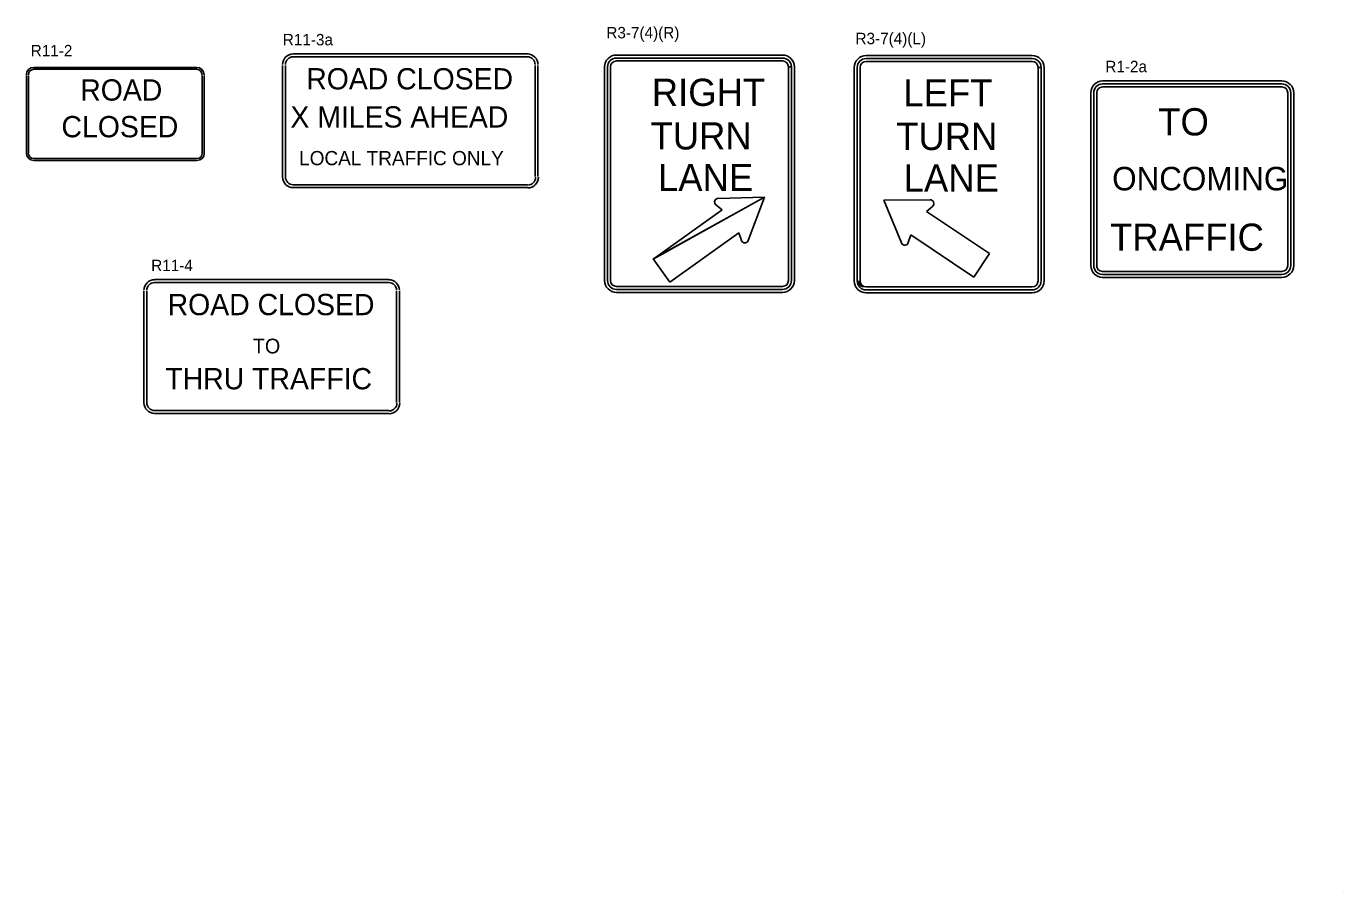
# Model space of a CAD drawing. Extents: x 1531.6 to 1538.58, y 1529.59 to 1539.33.
# Drawn here: x 1531.67 to 1538.58, y 1529.59 to 1534.14 of the extents above; entities that cross this region are included whole.
import ezdxf

# ---------------------------------------------------------------- set-up
doc = ezdxf.new("R2010")
doc.units = 0
for name, color, linetype in [('DETL-LINE', 7, 'Continuous'), ('DETL-NOTE', 7, 'Continuous'), ('TTLB-TEXT', 7, 'Continuous')]:
    doc.layers.add(name, color=color, linetype=linetype)

msp = doc.modelspace()

# ---------------------------------------------------------------- linework, layer by layer
at = {"layer": 'DETL-LINE'}
for p, q in [((1534.3016, 1533.9921), (1533.0731, 1533.9921)), ((1534.3016, 1533.9771), (1533.0731, 1533.9771)), ((1534.769, 1533.9859), (1535.6403, 1533.9859)), ((1534.769, 1533.9704), (1535.6403, 1533.9704)), ((1536.0788, 1533.9677), (1536.9501, 1533.9677)), ((1536.9502, 1533.9832), (1536.079, 1533.9832)), ((1536.9502, 1533.9676), (1536.079, 1533.9676)), ((1532.5663, 1533.9214), (1531.7123, 1533.9214)), ((1532.5663, 1533.9111), (1531.7123, 1533.9111)), ((1533.0173, 1533.9317), (1533.0173, 1533.3485)), ((1533.0322, 1533.9317), (1533.0322, 1533.3485)), ((1534.3425, 1533.3485), (1534.3425, 1533.9317)), ((1534.3574, 1533.3485), (1534.3574, 1533.9317)), ((1534.7068, 1532.8035), (1534.7068, 1533.9237)), ((1534.7224, 1532.8035), (1534.7224, 1533.9237)), ((1534.738, 1533.9237), (1534.738, 1532.8035)), ((1535.6403, 1533.9548), (1534.769, 1533.9548)), ((1535.687, 1533.9237), (1535.6714, 1533.9237)), ((1535.6714, 1532.8035), (1535.6714, 1533.9237)), ((1535.6714, 1533.9237), (1535.687, 1533.9237)), ((1535.687, 1533.9237), (1535.687, 1533.9237)), ((1535.687, 1533.9237), (1535.687, 1532.8035)), ((1535.7025, 1533.9237), (1535.7025, 1532.8035)), ((1536.0167, 1533.921), (1536.0167, 1532.8008)), ((1536.0322, 1533.921), (1536.0322, 1532.8008)), ((1536.0322, 1532.8008), (1536.0322, 1533.921)), ((1536.0478, 1533.921), (1536.0478, 1532.8008)), ((1536.0478, 1533.921), (1536.0478, 1532.8008)), ((1536.9501, 1533.9521), (1536.0788, 1533.9521)), ((1536.9502, 1533.9521), (1536.079, 1533.9521)), ((1536.9812, 1532.8008), (1536.9812, 1533.921)), ((1536.9812, 1533.921), (1536.9968, 1533.921)), ((1536.9813, 1532.8008), (1536.9813, 1533.921)), ((1536.9968, 1533.921), (1536.9968, 1532.8008)), ((1536.9969, 1532.8008), (1536.9969, 1533.921)), ((1537.0124, 1532.8008), (1537.0124, 1533.921)), ((1531.6734, 1533.8794), (1531.6734, 1533.4739)), ((1531.6838, 1533.8794), (1531.6838, 1533.4739)), ((1532.5948, 1533.4739), (1532.5948, 1533.8794)), ((1532.6052, 1533.4739), (1532.6052, 1533.8794)), ((1538.2602, 1533.8499), (1537.3198, 1533.8499)), ((1538.2602, 1533.8344), (1537.3198, 1533.8344)), ((1537.3198, 1533.8189), (1538.2602, 1533.8189)), ((1537.2575, 1533.7877), (1537.2575, 1532.882)), ((1537.2731, 1533.7877), (1537.2731, 1532.882)), ((1537.2886, 1532.882), (1537.2886, 1533.7877)), ((1538.2913, 1533.7877), (1538.2913, 1532.882)), ((1538.3069, 1532.882), (1538.3069, 1533.7877)), ((1538.3069, 1533.7877), (1538.3069, 1533.7877)), ((1538.3225, 1532.882), (1538.3225, 1533.7877)), ((1531.7123, 1533.4441), (1532.5663, 1533.4441)), ((1531.7123, 1533.4337), (1532.5663, 1533.4337)), ((1533.0731, 1533.3055), (1534.3016, 1533.3055)), ((1533.0731, 1533.2905), (1534.3016, 1533.2905)), ((1534.9609, 1532.9172), (1535.5451, 1533.2405)), ((1534.9626, 1532.915), (1535.5451, 1533.2405)), ((1535.2914, 1533.1998), (1535.3244, 1533.1736)), ((1535.5451, 1533.2405), (1535.303, 1533.2343)), ((1535.5451, 1533.2405), (1535.461, 1533.0133)), ((1536.4147, 1533.2265), (1536.1726, 1533.2248)), ((1536.1726, 1533.2248), (1536.264, 1533.0006)), ((1535.3244, 1533.1736), (1534.9626, 1532.915)), ((1536.3954, 1533.1651), (1536.4274, 1533.1924)), ((1536.726, 1532.9445), (1536.3954, 1533.1651)), ((1535.4104, 1533.0533), (1535.0485, 1532.7946)), ((1535.4246, 1533.0136), (1535.4104, 1533.0533)), ((1536.3004, 1533.002), (1536.3132, 1533.0421)), ((1536.3132, 1533.0421), (1536.6439, 1532.8215)), ((1536.6439, 1532.8215), (1536.726, 1532.9445)), ((1535.0485, 1532.7946), (1534.9609, 1532.9172)), ((1538.2608, 1532.8509), (1537.3182, 1532.8509)), ((1533.5744, 1532.8078), (1532.346, 1532.8078)), ((1533.5744, 1532.7929), (1532.346, 1532.7929)), ((1537.3198, 1532.8354), (1538.2608, 1532.8354)), ((1537.3198, 1532.8199), (1538.2602, 1532.8199)), ((1532.2901, 1532.7475), (1532.2901, 1532.1642)), ((1532.305, 1532.7475), (1532.305, 1532.1642)), ((1533.6153, 1532.1642), (1533.6153, 1532.7475)), ((1533.6302, 1532.1642), (1533.6302, 1532.7475)), ((1534.769, 1532.7724), (1535.6403, 1532.7724)), ((1535.6403, 1532.7569), (1534.769, 1532.7569)), ((1535.6403, 1532.7413), (1534.769, 1532.7413)), ((1536.0788, 1532.7697), (1536.9501, 1532.7697)), ((1536.9501, 1532.7542), (1536.0788, 1532.7542)), ((1536.079, 1532.7697), (1536.9502, 1532.7697)), ((1536.079, 1532.7541), (1536.9502, 1532.7541)), ((1536.079, 1532.7385), (1536.9502, 1532.7385)), ((1532.346, 1532.1213), (1533.5744, 1532.1213)), ((1532.346, 1532.1063), (1533.5744, 1532.1063))]:
    msp.add_line(p, q, dxfattribs=at)
for centre, radius, start, end in [((1533.0731, 1533.9362), 0.0558, 90, 180), ((1533.0731, 1533.9362), 0.0409, 90, 180), ((1534.3015, 1533.9362), 0.0558, 0, 90), ((1534.3015, 1533.9362), 0.0409, 0, 90), ((1534.7691, 1533.9237), 0.0622, 90, 180), ((1534.7691, 1533.9237), 0.0467, 90, 180), ((1535.6403, 1533.9237), 0.0622, 0, 90), ((1535.6403, 1533.9237), 0.0467, 0, 90), ((1536.0789, 1533.921), 0.0622, 90, 180), ((1536.0789, 1533.921), 0.0467, 90, 180), ((1536.0789, 1533.921), 0.0467, 90, 180), ((1536.9501, 1533.921), 0.0467, 0, 90), ((1536.9502, 1533.921), 0.0622, 0, 90), ((1536.9502, 1533.921), 0.0467, 0, 90), ((1531.7123, 1533.8826), 0.0388, 90, 180), ((1531.7123, 1533.8826), 0.0285, 90, 180), ((1532.5664, 1533.8826), 0.0388, 0, 90), ((1532.5664, 1533.8826), 0.0285, 0, 90), ((1534.7691, 1533.9237), 0.0311, 90, 180), ((1535.6403, 1533.9237), 0.0311, 0, 90), ((1536.0789, 1533.921), 0.0311, 90, 180), ((1536.0789, 1533.921), 0.0311, 90, 180), ((1536.9501, 1533.921), 0.0311, 0, 90), ((1536.9502, 1533.921), 0.0311, 0, 90), ((1537.3198, 1533.7877), 0.0622, 90, 180), ((1537.3198, 1533.7877), 0.0467, 90, 180), ((1537.3198, 1533.7877), 0.0311, 90, 180), ((1538.2602, 1533.7877), 0.0622, 0, 90), ((1538.2602, 1533.7877), 0.0467, 0, 90), ((1538.2602, 1533.7877), 0.0311, 0, 90), ((1531.712, 1533.472), 0.0388, 180, 270), ((1531.712, 1533.472), 0.0285, 180, 270), ((1532.5679, 1533.4713), 0.0388, 270, 0), ((1532.5679, 1533.4713), 0.0285, 270, 0), ((1533.0731, 1533.3465), 0.0558, 180, 270), ((1533.0731, 1533.3465), 0.0409, 180, 270), ((1534.3038, 1533.3446), 0.0558, 270, 0), ((1534.3038, 1533.3446), 0.0409, 270, 0), ((1535.3035, 1533.215), 0.0194, 91.44291, 231.51088), ((1536.4149, 1533.2072), 0.0194, 310.33715, 90.40512), ((1535.4428, 1533.0201), 0.0194, 199.60115, 339.66912), ((1536.2819, 1533.0079), 0.0194, 202.17891, 342.24688), ((1537.3198, 1532.8821), 0.0622, 180, 270), ((1537.3198, 1532.8821), 0.0467, 180, 270), ((1537.3193, 1532.8821), 0.0311, 180, 270), ((1538.2602, 1532.8821), 0.0622, 270, 0), ((1538.2602, 1532.8821), 0.0311, 270, 0), ((1538.2602, 1532.8821), 0.0467, 270, 0), ((1532.346, 1532.7519), 0.0558, 90, 180), ((1532.346, 1532.7519), 0.0409, 90, 180), ((1533.5744, 1532.7519), 0.0558, 0, 90), ((1533.5744, 1532.7519), 0.0409, 0, 90), ((1534.7691, 1532.8035), 0.0622, 180, 270), ((1534.7691, 1532.8035), 0.0467, 180, 270), ((1534.7691, 1532.8035), 0.0311, 180, 270), ((1535.6403, 1532.8035), 0.0622, 270, 0), ((1535.6403, 1532.8035), 0.0467, 270, 0), ((1535.6403, 1532.8035), 0.0311, 270, 0), ((1536.0789, 1532.8008), 0.0622, 180, 270), ((1536.0789, 1532.8008), 0.0467, 180, 270), ((1536.0789, 1532.8008), 0.0467, 180, 270), ((1536.0702, 1532.8008), 0.0311, 180, 270), ((1536.0789, 1532.8008), 0.0311, 180, 270), ((1536.9501, 1532.8008), 0.0467, 270, 0), ((1536.9501, 1532.8008), 0.0311, 270, 0), ((1536.9502, 1532.8008), 0.0311, 270, 0), ((1536.9502, 1532.8008), 0.0467, 270, 0), ((1536.9502, 1532.8008), 0.0622, 270, 0), ((1532.346, 1532.1622), 0.0558, 180, 270), ((1532.346, 1532.1622), 0.0409, 180, 270), ((1533.5766, 1532.1604), 0.0409, 270, 0), ((1533.5766, 1532.1604), 0.0558, 270, 0)]:
    msp.add_arc(centre, radius, start, end, dxfattribs=at)
at = {"layer": 'TTLB-TEXT'}
msp.add_line((1538.5844, 1529.5924), (1538.5844, 1529.5924), dxfattribs=at)

# ---------------------------------------------------------------- texts
at = {"layer": 'DETL-LINE'}
for s, height, p in [('ROAD CLOSED', 0.1115, (1533.1414, 1533.8057)), ('ROAD', 0.1115, (1531.9557, 1533.7471)), ('RIGHT', 0.14294, (1534.9547, 1533.719)), ('LEFT', 0.14294, (1536.2742, 1533.7162)), ('X MILES AHEAD', 0.1115, (1533.0584, 1533.6056)), ('TO', 0.14294, (1537.6118, 1533.5643)), ('CLOSED', 0.1115, (1531.8574, 1533.5547)), ('TURN', 0.14294, (1534.9479, 1533.4907)), ('TURN', 0.14294, (1536.237, 1533.4879)), ('LOCAL TRAFFIC ONLY', 0.07447, (1533.1044, 1533.4081)), ('LANE', 0.14294, (1534.9871, 1533.2721)), ('LANE', 0.14294, (1536.2762, 1533.2693)), ('ONCOMING', 0.12315, (1537.37, 1533.2762)), ('TRAFFIC', 0.14294, (1537.3589, 1532.9591)), ('ROAD CLOSED', 0.1115, (1532.4142, 1532.6215)), ('TO', 0.07721, (1532.8618, 1532.4209)), ('THRU TRAFFIC', 0.1115, (1532.402, 1532.2326))]:
    msp.add_text(s, height=height, dxfattribs=at).set_placement(p)
at = {"layer": 'DETL-NOTE'}
for s, p in [('R11-3a', (1533.0186, 1534.0368)), ('R3-7(4)(R)', (1534.7161, 1534.0733)), ('R3-7(4)(L)', (1536.0232, 1534.0428)), ('R11-2', (1531.696, 1533.979)), ('R1-2a', (1537.3341, 1533.8957)), ('R11-4', (1532.3281, 1532.8525))]:
    msp.add_text(s, height=0.06, dxfattribs=at).set_placement(p)

doc.saveas('drawing.dxf')
